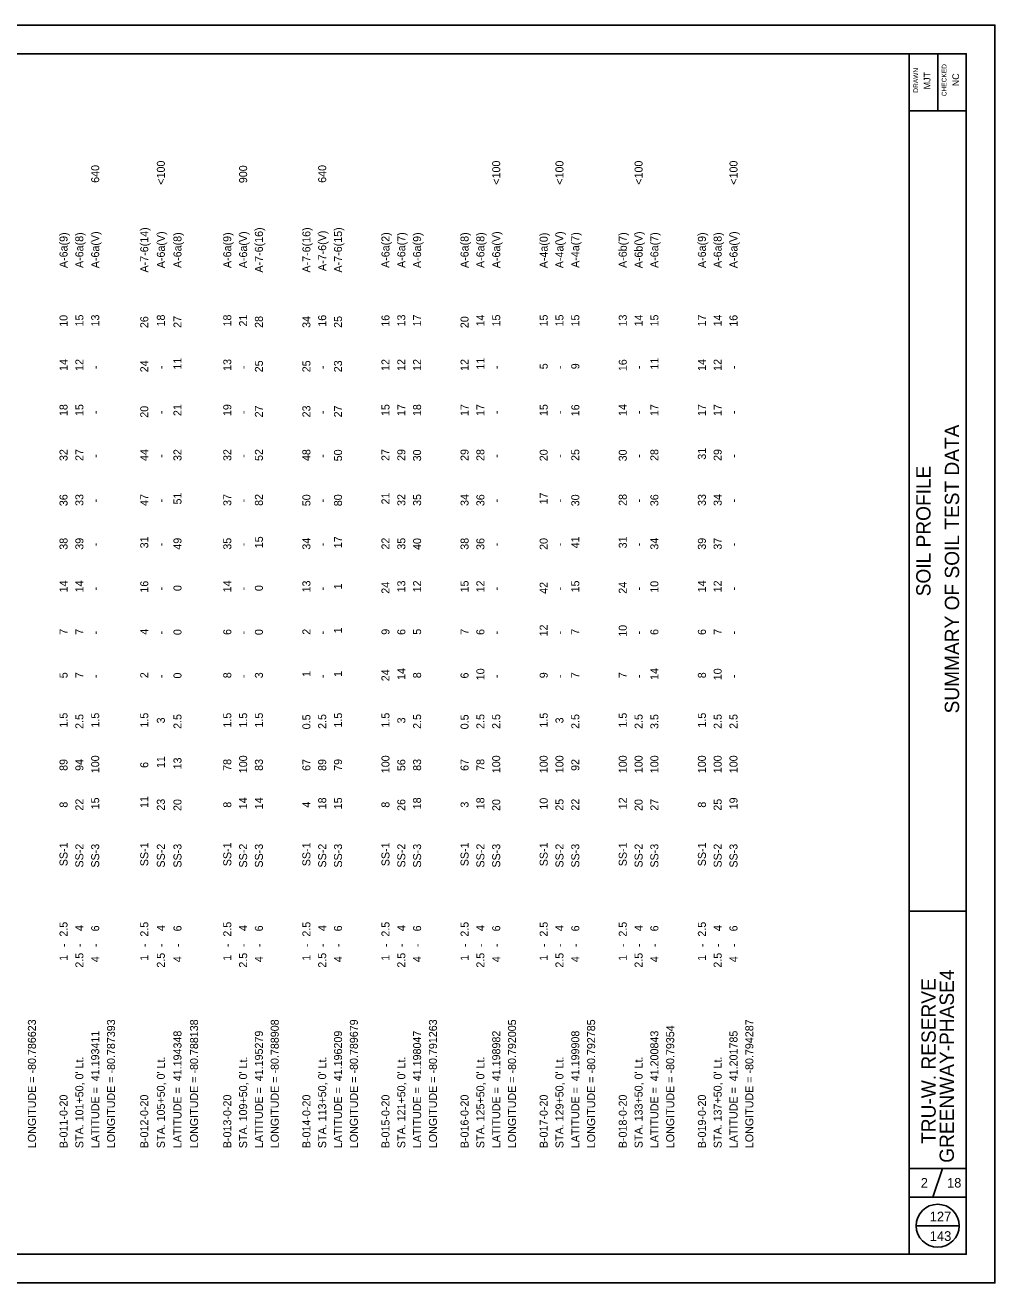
# Model space of a CAD drawing. Extents: x 0 to 83.4, y 4.5 to 46.4.
# Drawn here: x 17.04 to 34, y 24.4 to 46.4 of the extents above; entities that cross this region are included whole.
import ezdxf

# ---------------------------------------------------------------- set-up
doc = ezdxf.new("R2010")
doc.units = 0
for name, color, linetype in [('SH_Border', 7, 'Continuous'), ('SH_Cut_Line', 7, 'Continuous'), ('SH_Data', 7, 'Continuous'), ('TX_P_1', 7, 'Continuous')]:
    doc.layers.add(name, color=color, linetype=linetype)

msp = doc.modelspace()

# ---------------------------------------------------------------- linework, layer by layer
at = {"layer": 'SH_Border'}
for p, q in [((32.5, 24.904), (32.5, 45.904)), ((33, 44.904), (33, 45.904)), ((32.5, 44.904), (33.5, 44.904)), ((32.5, 30.904), (33.5, 30.904)), ((32.5, 26.404), (33.5, 26.404)), ((32.917, 25.904), (33.083, 26.404)), ((32.5, 25.904), (33.5, 25.904))]:
    msp.add_line(p, q, dxfattribs=at)
msp.add_lwpolyline([(2, 45.904), (33.5, 45.904), (33.5, 24.904), (2, 24.904)], close=True, dxfattribs=at)
at = {"layer": 'SH_Cut_Line'}
msp.add_lwpolyline([(0, 24.404), (34, 24.404), (34, 46.404), (0, 46.404)], close=True, dxfattribs=at)
at = {"layer": 'SH_Data'}
msp.add_line((32.625, 25.404), (33.375, 25.404), dxfattribs=at)
msp.add_circle((33, 25.404), 0.375, dxfattribs=at)

# ---------------------------------------------------------------- texts
for s, height, p in [('DRAWN', 0.0833, (32.658, 45.222)), ('MJT', 0.1167, (32.874, 45.281)), ('CHECKED', 0.0833, (33.154, 45.161)), ('NC', 0.1167, (33.374, 45.336)), ('SUMMARY OF SOIL TEST DATA', 0.25, (33.375, 34.365)), ('SOIL PROFILE', 0.25, (32.875, 36.413)), ('TRU-W. RESERVE', 0.25, (32.966, 26.835)), ('GREENWAY-PHASE4', 0.25, (33.284, 26.504))]:
    msp.add_text(s, height=height, rotation=90, dxfattribs=at).set_placement(p)
for s, height, p in [('2', 0.167, (32.705, 26.071)), ('18', 0.1666, (33.166, 26.071)), ('127', 0.17, (32.86, 25.479)), ('143', 0.17, (32.86, 25.137))]:
    msp.add_text(s, height=height, dxfattribs=at).set_placement(p)
at = {"layer": 'TX_P_1'}
for s, p in [('<100', (19.483, 43.613)), ('<100', (25.349, 43.613)), ('<100', (26.455, 43.613)), ('<100', (27.839, 43.613)), ('<100', (29.499, 43.613)), ('640', (18.335, 43.646)), ('900', (20.922, 43.64)), ('640', (22.305, 43.646)), ('A-6a(9)', (17.781, 42.155)), ('A-6a(8)', (18.058, 42.156)), ('A-6a(V)', (18.335, 42.152)), ('A-7-6(14)', (19.193, 42.077)), ('A-6a(V)', (19.483, 42.152)), ('A-6a(8)', (19.774, 42.156)), ('A-6a(9)', (20.645, 42.155)), ('A-6a(V)', (20.922, 42.152)), ('A-7-6(16)', (21.198, 42.076)), ('A-7-6(16)', (22.029, 42.076)), ('A-7-6(V)', (22.305, 42.103)), ('A-7-6(15)', (22.582, 42.077)), ('A-6a(2)', (23.412, 42.157)), ('A-6a(7)', (23.689, 42.157)), ('A-6a(9)', (23.965, 42.155)), ('A-6a(8)', (24.795, 42.156)), ('A-6a(8)', (25.072, 42.156)), ('A-6a(V)', (25.349, 42.152)), ('A-4a(0)', (26.179, 42.151)), ('A-4a(V)', (26.455, 42.152)), ('A-4a(7)', (26.732, 42.158)), ('A-6b(7)', (27.562, 42.157)), ('A-6b(V)', (27.839, 42.151)), ('A-6a(7)', (28.115, 42.157)), ('A-6a(9)', (28.946, 42.155)), ('A-6a(8)', (29.222, 42.156)), ('A-6a(V)', (29.499, 42.152)), ('10', (17.781, 41.128)), ('15', (18.058, 41.133)), ('13', (18.335, 41.133)), ('26', (19.193, 41.105)), ('18', (19.483, 41.133)), ('27', (19.774, 41.109)), ('18', (20.645, 41.133)), ('21', (20.922, 41.133)), ('28', (21.198, 41.109)), ('34', (22.029, 41.108)), ('16', (22.305, 41.129)), ('25', (22.582, 41.109)), ('16', (23.412, 41.129)), ('13', (23.689, 41.133)), ('17', (23.965, 41.133)), ('20', (24.795, 41.104)), ('14', (25.072, 41.134)), ('15', (25.349, 41.133)), ('15', (26.179, 41.133)), ('15', (26.455, 41.133)), ('15', (26.732, 41.133)), ('13', (27.562, 41.133)), ('14', (27.839, 41.134)), ('15', (28.115, 41.133)), ('17', (28.946, 41.133)), ('14', (29.222, 41.134)), ('16', (29.499, 41.129)), ('14', (17.781, 40.356)), ('12', (18.058, 40.356)), ('24', (19.193, 40.332)), ('11', (19.774, 40.379)), ('13', (20.645, 40.356)), ('25', (21.198, 40.332)), ('25', (22.029, 40.332)), ('23', (22.582, 40.332)), ('12', (23.412, 40.356)), ('12', (23.689, 40.356)), ('12', (23.965, 40.356)), ('12', (24.795, 40.356)), ('11', (25.072, 40.379)), ('5', (26.179, 40.385)), ('9', (26.732, 40.385)), ('16', (27.562, 40.352)), ('11', (28.115, 40.379)), ('14', (28.946, 40.356)), ('12', (29.222, 40.356)), ('-', (18.335, 40.389)), ('-', (19.483, 40.389)), ('-', (20.922, 40.389)), ('-', (22.305, 40.389)), ('-', (25.349, 40.389)), ('-', (26.455, 40.389)), ('-', (27.839, 40.389)), ('-', (29.499, 40.389)), ('18', (17.781, 39.566)), ('15', (18.058, 39.566)), ('-', (18.335, 39.6)), ('20', (19.193, 39.537)), ('-', (19.483, 39.6)), ('21', (19.774, 39.566)), ('19', (20.645, 39.566)), ('-', (20.922, 39.6)), ('27', (21.198, 39.543)), ('23', (22.029, 39.543)), ('-', (22.305, 39.6)), ('27', (22.582, 39.543)), ('15', (23.412, 39.566)), ('17', (23.689, 39.566)), ('18', (23.965, 39.566)), ('17', (24.795, 39.566)), ('17', (25.072, 39.566)), ('-', (25.349, 39.6)), ('15', (26.179, 39.566)), ('-', (26.455, 39.6)), ('16', (26.732, 39.562)), ('14', (27.562, 39.567)), ('-', (27.839, 39.6)), ('17', (28.115, 39.566)), ('17', (28.946, 39.566)), ('17', (29.222, 39.566)), ('-', (29.499, 39.6)), ('32', (17.781, 38.78)), ('27', (18.058, 38.781)), ('44', (19.193, 38.78)), ('32', (19.774, 38.78)), ('32', (20.645, 38.78)), ('52', (21.198, 38.781)), ('48', (22.029, 38.779)), ('50', (22.582, 38.775)), ('27', (23.412, 38.781)), ('29', (23.689, 38.781)), ('30', (23.965, 38.774)), ('29', (24.795, 38.781)), ('28', (25.072, 38.781)), ('20', (26.179, 38.776)), ('25', (26.732, 38.781)), ('30', (27.562, 38.774)), ('28', (28.115, 38.781)), ('31', (28.946, 38.803)), ('29', (29.222, 38.781)), ('-', (18.335, 38.838)), ('-', (19.483, 38.838)), ('-', (20.922, 38.838)), ('-', (22.305, 38.838)), ('-', (25.349, 38.838)), ('-', (26.455, 38.838)), ('-', (27.839, 38.838)), ('-', (29.499, 38.838)), ('36', (17.781, 37.99)), ('33', (18.058, 37.994)), ('-', (18.335, 38.053)), ('47', (19.193, 37.994)), ('-', (19.483, 38.053)), ('51', (19.774, 38.019)), ('37', (20.645, 37.994)), ('-', (20.922, 38.053)), ('82', (21.198, 37.995)), ('50', (22.029, 37.989)), ('-', (22.305, 38.053)), ('80', (22.582, 37.989)), ('21', (23.412, 38.02)), ('32', (23.689, 37.994)), ('35', (23.965, 37.994)), ('34', (24.795, 37.994)), ('36', (25.072, 37.99)), ('-', (25.349, 38.053)), ('17', (26.179, 38.02)), ('-', (26.455, 38.053)), ('30', (26.732, 37.988)), ('28', (27.562, 37.995)), ('-', (27.839, 38.053)), ('36', (28.115, 37.99)), ('33', (28.946, 37.994)), ('34', (29.222, 37.994)), ('-', (29.499, 38.053)), ('38', (17.781, 37.228)), ('39', (18.058, 37.228)), ('31', (19.193, 37.252)), ('49', (19.774, 37.229)), ('35', (20.645, 37.229)), ('15', (21.198, 37.254)), ('34', (22.029, 37.229)), ('17', (22.582, 37.254)), ('22', (23.412, 37.231)), ('35', (23.689, 37.229)), ('40', (23.965, 37.224)), ('38', (24.795, 37.228)), ('36', (25.072, 37.225)), ('20', (26.179, 37.225)), ('41', (26.732, 37.253)), ('31', (27.562, 37.252)), ('34', (28.115, 37.229)), ('39', (28.946, 37.228)), ('37', (29.222, 37.229)), ('-', (18.335, 37.288)), ('-', (19.483, 37.288)), ('-', (20.922, 37.288)), ('-', (22.305, 37.288)), ('-', (25.349, 37.288)), ('-', (26.455, 37.288)), ('-', (27.839, 37.288)), ('-', (29.499, 37.288)), ('14', (17.781, 36.482)), ('14', (18.058, 36.482)), ('-', (18.335, 36.514)), ('16', (19.193, 36.477)), ('-', (19.483, 36.514)), ('0', (19.774, 36.505)), ('14', (20.645, 36.482)), ('-', (20.922, 36.514)), ('0', (21.198, 36.505)), ('13', (22.029, 36.481)), ('-', (22.305, 36.514)), ('1', (22.582, 36.535)), ('24', (23.412, 36.458)), ('13', (23.689, 36.481)), ('12', (23.965, 36.482)), ('15', (24.795, 36.481)), ('12', (25.072, 36.482)), ('-', (25.349, 36.514)), ('42', (26.179, 36.456)), ('-', (26.455, 36.514)), ('15', (26.732, 36.481)), ('24', (27.562, 36.458)), ('-', (27.839, 36.514)), ('10', (28.115, 36.476)), ('14', (28.946, 36.482)), ('12', (29.222, 36.482)), ('-', (29.499, 36.514)), ('12', (26.179, 35.711)), ('10', (27.562, 35.705)), ('7', (17.781, 35.741)), ('7', (18.058, 35.741)), ('-', (18.335, 35.744)), ('4', (19.193, 35.741)), ('-', (19.483, 35.744)), ('0', (19.774, 35.735)), ('6', (20.645, 35.737)), ('-', (20.922, 35.744)), ('0', (21.198, 35.735)), ('2', (22.029, 35.741)), ('-', (22.305, 35.744)), ('1', (22.582, 35.764)), ('9', (23.412, 35.74)), ('6', (23.689, 35.737)), ('5', (23.965, 35.741)), ('7', (24.795, 35.741)), ('6', (25.072, 35.737)), ('-', (25.349, 35.744)), ('-', (26.455, 35.744)), ('7', (26.732, 35.741)), ('-', (27.839, 35.744)), ('6', (28.115, 35.737)), ('6', (28.946, 35.737)), ('7', (29.222, 35.741)), ('-', (29.499, 35.744)), ('5', (17.781, 34.98)), ('7', (18.058, 34.98)), ('-', (18.335, 34.984)), ('2', (19.193, 34.981)), ('-', (19.483, 34.984)), ('0', (19.774, 34.975)), ('8', (20.645, 34.98)), ('-', (20.922, 34.984)), ('3', (21.198, 34.98)), ('1', (22.029, 35.004)), ('-', (22.305, 34.984)), ('1', (22.582, 35.004)), ('24', (23.412, 34.927)), ('14', (23.689, 34.951)), ('8', (23.965, 34.98)), ('6', (24.795, 34.976)), ('10', (25.072, 34.945)), ('-', (25.349, 34.984)), ('9', (26.179, 34.98)), ('-', (26.455, 34.984)), ('7', (26.732, 34.98)), ('7', (27.562, 34.98)), ('-', (27.839, 34.984)), ('14', (28.115, 34.951)), ('8', (28.946, 34.98)), ('10', (29.222, 34.945)), ('-', (29.499, 34.984)), ('1.5', (17.781, 34.117)), ('2.5', (18.058, 34.094)), ('1.5', (18.335, 34.117)), ('1.5', (19.193, 34.117)), ('2.5', (19.774, 34.094)), ('1.5', (20.645, 34.117)), ('1.5', (20.922, 34.117)), ('1.5', (21.198, 34.117)), ('0.5', (22.029, 34.087)), ('2.5', (22.305, 34.094)), ('1.5', (22.582, 34.117)), ('1.5', (23.412, 34.117)), ('2.5', (23.965, 34.094)), ('0.5', (24.795, 34.087)), ('2.5', (25.072, 34.094)), ('2.5', (25.349, 34.094)), ('1.5', (26.179, 34.117)), ('2.5', (26.732, 34.094)), ('1.5', (27.562, 34.117)), ('2.5', (27.839, 34.094)), ('3.5', (28.115, 34.092)), ('1.5', (28.946, 34.117)), ('2.5', (29.222, 34.094)), ('2.5', (29.499, 34.094)), ('3', (19.483, 34.19)), ('3', (23.689, 34.19)), ('3', (26.455, 34.19)), ('89', (17.781, 33.359)), ('94', (18.058, 33.359)), ('100', (18.335, 33.319)), ('6', (19.193, 33.411)), ('11', (19.483, 33.408)), ('13', (19.774, 33.385)), ('78', (20.645, 33.36)), ('100', (20.922, 33.319)), ('83', (21.198, 33.36)), ('67', (22.029, 33.359)), ('89', (22.305, 33.359)), ('79', (22.582, 33.36)), ('100', (23.412, 33.319)), ('56', (23.689, 33.356)), ('83', (23.965, 33.36)), ('67', (24.795, 33.359)), ('78', (25.072, 33.36)), ('100', (25.349, 33.319)), ('100', (26.179, 33.319)), ('100', (26.455, 33.319)), ('92', (26.732, 33.359)), ('100', (27.562, 33.319)), ('100', (27.839, 33.319)), ('100', (28.115, 33.319)), ('100', (28.946, 33.319)), ('100', (29.222, 33.319)), ('100', (29.499, 33.319)), ('8', (17.781, 32.716)), ('22', (18.058, 32.664)), ('15', (18.335, 32.687)), ('11', (19.193, 32.711)), ('23', (19.483, 32.663)), ('20', (19.774, 32.658)), ('8', (20.645, 32.716)), ('14', (20.922, 32.687)), ('14', (21.198, 32.687)), ('4', (22.029, 32.717)), ('18', (22.305, 32.687)), ('15', (22.582, 32.687)), ('8', (23.412, 32.716)), ('26', (23.689, 32.659)), ('18', (23.965, 32.687)), ('3', (24.795, 32.717)), ('18', (25.072, 32.687)), ('20', (25.349, 32.658)), ('10', (26.179, 32.682)), ('25', (26.455, 32.663)), ('22', (26.732, 32.664)), ('12', (27.562, 32.687)), ('20', (27.839, 32.658)), ('27', (28.115, 32.663)), ('8', (28.946, 32.716)), ('25', (29.222, 32.663)), ('19', (29.499, 32.687)), ('SS-1', (17.781, 31.692)), ('SS-2', (18.058, 31.669)), ('SS-3', (18.335, 31.668)), ('SS-1', (19.193, 31.692)), ('SS-2', (19.483, 31.669)), ('SS-3', (19.774, 31.668)), ('SS-1', (20.645, 31.692)), ('SS-2', (20.922, 31.669)), ('SS-3', (21.198, 31.668)), ('SS-1', (22.029, 31.692)), ('SS-2', (22.305, 31.669)), ('SS-3', (22.582, 31.668)), ('SS-1', (23.412, 31.692)), ('SS-2', (23.689, 31.669)), ('SS-3', (23.965, 31.668)), ('SS-1', (24.795, 31.692)), ('SS-2', (25.072, 31.669)), ('SS-3', (25.349, 31.668)), ('SS-1', (26.179, 31.692)), ('SS-2', (26.455, 31.669)), ('SS-3', (26.732, 31.668)), ('SS-1', (27.562, 31.692)), ('SS-2', (27.839, 31.669)), ('SS-3', (28.115, 31.668)), ('SS-1', (28.946, 31.692)), ('SS-2', (29.222, 31.669)), ('SS-3', (29.499, 31.668)), ('2.5', (17.781, 30.46)), ('4', (18.058, 30.557)), ('6', (18.335, 30.552)), ('2.5', (19.193, 30.46)), ('4', (19.483, 30.557)), ('6', (19.774, 30.552)), ('2.5', (20.645, 30.46)), ('4', (20.922, 30.557)), ('6', (21.198, 30.552)), ('2.5', (22.029, 30.46)), ('4', (22.305, 30.557)), ('6', (22.582, 30.552)), ('2.5', (23.412, 30.46)), ('4', (23.689, 30.557)), ('6', (23.965, 30.552)), ('2.5', (24.795, 30.46)), ('4', (25.072, 30.557)), ('6', (25.349, 30.552)), ('2.5', (26.179, 30.46)), ('4', (26.455, 30.557)), ('6', (26.732, 30.552)), ('2.5', (27.562, 30.46)), ('4', (27.839, 30.557)), ('6', (28.115, 30.552)), ('2.5', (28.946, 30.46)), ('4', (29.222, 30.557)), ('6', (29.499, 30.552)), ('-', (17.781, 30.276)), ('2.5', (18.058, 29.917)), ('-', (18.058, 30.276)), ('-', (18.335, 30.276)), ('-', (19.193, 30.276)), ('2.5', (19.483, 29.917)), ('-', (19.483, 30.276)), ('-', (19.774, 30.276)), ('-', (20.645, 30.276)), ('2.5', (20.922, 29.917)), ('-', (20.922, 30.276)), ('-', (21.198, 30.276)), ('-', (22.029, 30.276)), ('2.5', (22.305, 29.917)), ('-', (22.305, 30.276)), ('-', (22.582, 30.276)), ('-', (23.412, 30.276)), ('2.5', (23.689, 29.917)), ('-', (23.689, 30.276)), ('-', (23.965, 30.276)), ('-', (24.795, 30.276)), ('2.5', (25.072, 29.917)), ('-', (25.072, 30.276)), ('-', (25.349, 30.276)), ('-', (26.179, 30.276)), ('2.5', (26.455, 29.917)), ('-', (26.455, 30.276)), ('-', (26.732, 30.276)), ('-', (27.562, 30.276)), ('2.5', (27.839, 29.917)), ('-', (27.839, 30.276)), ('-', (28.115, 30.276)), ('-', (28.946, 30.276)), ('2.5', (29.222, 29.917)), ('-', (29.222, 30.276)), ('-', (29.499, 30.276)), ('1', (17.781, 30.037)), ('4', (18.335, 30.013)), ('1', (19.193, 30.037)), ('4', (19.774, 30.013)), ('1', (20.645, 30.037)), ('4', (21.198, 30.013)), ('1', (22.029, 30.037)), ('4', (22.582, 30.013)), ('1', (23.412, 30.037)), ('4', (23.965, 30.013)), ('1', (24.795, 30.037)), ('4', (25.349, 30.013)), ('1', (26.179, 30.037)), ('4', (26.732, 30.013)), ('1', (27.562, 30.037)), ('4', (28.115, 30.013)), ('1', (28.946, 30.037)), ('4', (29.499, 30.013)), ('LONGITUDE = -80.786623', (17.228, 26.76)), ('LONGITUDE = -80.787393', (18.612, 26.76)), ('LONGITUDE = -80.788138', (20.064, 26.76)), ('LONGITUDE = -80.788908', (21.475, 26.76)), ('LONGITUDE = -80.789679', (22.859, 26.76)), ('LONGITUDE = -80.791263', (24.242, 26.76)), ('LONGITUDE = -80.792005', (25.625, 26.76)), ('LONGITUDE = -80.792785', (27.009, 26.76)), ('LONGITUDE = -80.79354', (28.392, 26.76)), ('LONGITUDE = -80.794287', (29.776, 26.76)), ('LATITUDE =  41.193411', (18.335, 26.76)), ('LATITUDE =  41.194348', (19.774, 26.76)), ('LATITUDE =  41.195279', (21.198, 26.76)), ('LATITUDE =  41.196209', (22.582, 26.76)), ('LATITUDE =  41.198047', (23.965, 26.76)), ('LATITUDE =  41.198982', (25.349, 26.76)), ('LATITUDE =  41.199908', (26.732, 26.76)), ('LATITUDE =  41.200843', (28.115, 26.76)), ('LATITUDE =  41.201785', (29.499, 26.76)), ("STA. 101+50, 0' Lt.", (18.058, 26.76)), ("STA. 105+50, 0' Lt.", (19.483, 26.76)), ("STA. 109+50, 0' Lt.", (20.922, 26.76)), ("STA. 113+50, 0' Lt.", (22.305, 26.76)), ("STA. 121+50, 0' Lt.", (23.689, 26.76)), ("STA. 125+50, 0' Lt.", (25.072, 26.76)), ("STA. 129+50, 0' Lt.", (26.455, 26.76)), ("STA. 133+50, 0' Lt.", (27.839, 26.76)), ("STA. 137+50, 0' Lt.", (29.222, 26.76)), ('B-011-0-20', (17.781, 26.76)), ('B-012-0-20', (19.193, 26.76)), ('B-013-0-20', (20.645, 26.76)), ('B-014-0-20', (22.029, 26.76)), ('B-015-0-20', (23.412, 26.76)), ('B-016-0-20', (24.795, 26.76)), ('B-017-0-20', (26.179, 26.76)), ('B-018-0-20', (27.562, 26.76)), ('B-019-0-20', (28.946, 26.76))]:
    msp.add_text(s, height=0.14, rotation=90, dxfattribs=at).set_placement(p)

doc.saveas('drawing.dxf')
